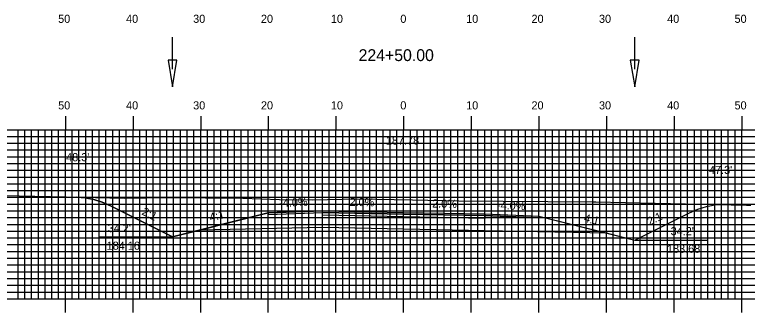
# Model space of a CAD drawing. Extents: x 1797994 to 1798337, y 442591 to 442811.
# Drawn here: x 1798102.5 to 1798210.8, y 442696.7 to 442740.7 of the extents above; entities that cross this region are included whole.
import ezdxf

# ---------------------------------------------------------------- set-up
doc = ezdxf.new("R2010")
doc.units = 0
for name, color, linetype in [('ANNOTATION', 7, 'Continuous'), ('D_Drainage_Ditch_Line', 7, 'Continuous'), ('D_Roadway_Centerline', 7, 'Continuous'), ('D_Roadway_Centerline_Text', 7, 'Continuous'), ('D_Roadway_Edge_Shoulder', 7, 'Continuous'), ('D_Roadway_Edge_TW', 7, 'Continuous'), ('D_Roadway_Pavement', 7, 'Continuous'), ('D_Roadway_SlopeLines', 7, 'Continuous'), ('D_Roadway_SubGrade', 7, 'Continuous'), ('D_Text_Standard', 7, 'Continuous'), ('H_V ANNOTATION', 7, 'Continuous'), ('MAJOR', 7, 'Continuous'), ('MINOR', 7, 'Continuous'), ('PDRAIN', 7, 'Continuous'), ('S_Roadway_Centerline', 7, 'Continuous')]:
    doc.layers.add(name, color=color, linetype=linetype)

msp = doc.modelspace()

# ---------------------------------------------------------------- linework, layer by layer
at = {"layer": 'D_Drainage_Ditch_Line'}
for p, q in [((1798125.78, 442732.63), (1798125.78, 442737.33)), ((1798194.13, 442732.63), (1798194.13, 442737.33))]:
    msp.add_line(p, q, dxfattribs=at)
for points in [[(1798126.44, 442733.94), (1798125.13, 442733.94), (1798125.78, 442730)], [(1798194.79, 442733.94), (1798193.48, 442733.94), (1798194.13, 442730)]]:
    msp.add_lwpolyline(points, close=True, dxfattribs=at)
at = {"layer": 'D_Roadway_Centerline'}
msp.add_lwpolyline([(1798111.64, 442713.71), (1798112.89, 442713.6), (1798114.14, 442713.35), (1798115.39, 442712.95), (1798116.64, 442712.4), (1798125.78, 442707.83), (1798129.78, 442708.83), (1798139.96, 442711.37), (1798147.96, 442711.69), (1798159.96, 442711.45), (1798171.96, 442711.21), (1798179.96, 442710.89), (1798190.13, 442708.35), (1798194.13, 442707.35), (1798202.23, 442711.4), (1798203.48, 442711.94), (1798204.73, 442712.32), (1798205.98, 442712.54), (1798207.23, 442712.59)], dxfattribs=at)
at = {"layer": 'D_Roadway_Edge_Shoulder'}
for points in [[(1798147.96, 442711.69), (1798139.96, 442711.37), (1798139.96, 442711.12), (1798147.96, 442711.44)], [(1798171.96, 442711.21), (1798179.96, 442710.89), (1798179.96, 442710.64), (1798171.96, 442710.96)]]:
    msp.add_lwpolyline(points, close=True, dxfattribs=at)
at = {"layer": 'D_Roadway_Edge_TW'}
msp.add_lwpolyline([(1798147.96, 442711.44), (1798147.96, 442711.69), (1798159.96, 442711.45), (1798171.96, 442711.21), (1798171.96, 442710.96), (1798159.96, 442711.2)], close=True, dxfattribs=at)
at = {"layer": 'D_Roadway_Pavement'}
msp.add_lwpolyline([(1798147.96, 442711.02), (1798147.96, 442711.44), (1798159.96, 442711.2), (1798171.96, 442710.96), (1798171.96, 442710.54), (1798159.96, 442710.78)], close=True, dxfattribs=at)
at = {"layer": 'D_Roadway_SlopeLines'}
for points in [[(1798125.78, 442707.83), (1798116.64, 442712.4), (1798115.39, 442712.95), (1798114.14, 442713.35), (1798112.89, 442713.6), (1798111.64, 442713.71)], [(1798194.13, 442707.35), (1798202.23, 442711.4), (1798203.48, 442711.94), (1798204.73, 442712.32), (1798205.98, 442712.54), (1798207.23, 442712.59)], [(1798139.96, 442711.37), (1798125.78, 442707.83)], [(1798179.96, 442710.89), (1798194.13, 442707.35)]]:
    msp.add_lwpolyline(points, dxfattribs=at)
at = {"layer": 'D_Roadway_SubGrade'}
msp.add_lwpolyline([(1798147.96, 442709.19), (1798129.78, 442708.83), (1798139.96, 442711.37), (1798139.96, 442711.12), (1798147.96, 442711.44), (1798159.96, 442711.2), (1798171.96, 442710.96), (1798179.96, 442710.64), (1798179.96, 442710.89), (1798190.13, 442708.35), (1798171.96, 442708.71), (1798159.96, 442708.95)], close=True, dxfattribs=at)
at = {"layer": 'MAJOR'}
for p, q in [((1798109.96, 442725.67), (1798109.96, 442723.67)), ((1798119.96, 442725.67), (1798119.96, 442723.67)), ((1798129.96, 442725.67), (1798129.96, 442723.67)), ((1798139.96, 442725.67), (1798139.96, 442723.67)), ((1798149.96, 442725.67), (1798149.96, 442723.67)), ((1798159.96, 442725.67), (1798159.96, 442723.67)), ((1798169.96, 442725.67), (1798169.96, 442723.67)), ((1798179.96, 442725.67), (1798179.96, 442723.67)), ((1798189.96, 442725.67), (1798189.96, 442723.67)), ((1798199.96, 442725.67), (1798199.96, 442723.67)), ((1798209.96, 442725.67), (1798209.96, 442723.67)), ((1798019.96, 442723.67), (1798299.96, 442723.67)), ((1798019.96, 442723.67), (1798299.96, 442723.67)), ((1798109.96, 442698.67), (1798109.96, 442723.67)), ((1798119.96, 442698.67), (1798119.96, 442723.67)), ((1798129.96, 442698.67), (1798129.96, 442723.67)), ((1798139.96, 442698.67), (1798139.96, 442723.67)), ((1798149.96, 442698.67), (1798149.96, 442723.67)), ((1798159.96, 442698.67), (1798159.96, 442723.67)), ((1798169.96, 442698.67), (1798169.96, 442723.67)), ((1798179.96, 442698.67), (1798179.96, 442723.67)), ((1798189.96, 442698.67), (1798189.96, 442723.67)), ((1798199.96, 442698.67), (1798199.96, 442723.67)), ((1798209.96, 442698.67), (1798209.96, 442723.67)), ((1798019.96, 442718.67), (1798299.96, 442718.67)), ((1798019.96, 442713.67), (1798299.96, 442713.67)), ((1798019.96, 442708.67), (1798299.96, 442708.67)), ((1798019.96, 442703.67), (1798299.96, 442703.67)), ((1798019.96, 442698.67), (1798299.96, 442698.67)), ((1798019.96, 442698.67), (1798299.96, 442698.67)), ((1798109.96, 442696.66), (1798109.96, 442698.67)), ((1798119.96, 442696.66), (1798119.96, 442698.67)), ((1798129.96, 442696.66), (1798129.96, 442698.67)), ((1798139.96, 442696.66), (1798139.96, 442698.67)), ((1798149.96, 442696.66), (1798149.96, 442698.67)), ((1798159.96, 442696.66), (1798159.96, 442698.67)), ((1798169.96, 442696.66), (1798169.96, 442698.67)), ((1798179.96, 442696.66), (1798179.96, 442698.67)), ((1798189.96, 442696.66), (1798189.96, 442698.67)), ((1798199.96, 442696.66), (1798199.96, 442698.67)), ((1798209.96, 442696.66), (1798209.96, 442698.67))]:
    msp.add_line(p, q, dxfattribs=at)
at = {"layer": 'MINOR'}
for p, q in [((1798102.96, 442698.67), (1798102.96, 442723.67)), ((1798103.96, 442698.67), (1798103.96, 442723.67)), ((1798104.96, 442698.67), (1798104.96, 442723.67)), ((1798105.96, 442698.67), (1798105.96, 442723.67)), ((1798106.96, 442698.67), (1798106.96, 442723.67)), ((1798107.96, 442698.67), (1798107.96, 442723.67)), ((1798108.96, 442698.67), (1798108.96, 442723.67)), ((1798110.96, 442698.67), (1798110.96, 442723.67)), ((1798111.96, 442698.67), (1798111.96, 442723.67)), ((1798112.96, 442698.67), (1798112.96, 442723.67)), ((1798113.96, 442698.67), (1798113.96, 442723.67)), ((1798114.96, 442698.67), (1798114.96, 442723.67)), ((1798115.96, 442698.67), (1798115.96, 442723.67)), ((1798116.96, 442698.67), (1798116.96, 442723.67)), ((1798117.96, 442698.67), (1798117.96, 442723.67)), ((1798118.96, 442698.67), (1798118.96, 442723.67)), ((1798120.96, 442698.67), (1798120.96, 442723.67)), ((1798121.96, 442698.67), (1798121.96, 442723.67)), ((1798122.96, 442698.67), (1798122.96, 442723.67)), ((1798123.96, 442698.67), (1798123.96, 442723.67)), ((1798124.96, 442698.67), (1798124.96, 442723.67)), ((1798125.96, 442698.67), (1798125.96, 442723.67)), ((1798126.96, 442698.67), (1798126.96, 442723.67)), ((1798127.96, 442698.67), (1798127.96, 442723.67)), ((1798128.96, 442698.67), (1798128.96, 442723.67)), ((1798130.96, 442698.67), (1798130.96, 442723.67)), ((1798131.96, 442698.67), (1798131.96, 442723.67)), ((1798132.96, 442698.67), (1798132.96, 442723.67)), ((1798133.96, 442698.67), (1798133.96, 442723.67)), ((1798134.96, 442698.67), (1798134.96, 442723.67)), ((1798135.96, 442698.67), (1798135.96, 442723.67)), ((1798136.96, 442698.67), (1798136.96, 442723.67)), ((1798137.96, 442698.67), (1798137.96, 442723.67)), ((1798138.96, 442698.67), (1798138.96, 442723.67)), ((1798140.96, 442698.67), (1798140.96, 442723.67)), ((1798141.96, 442698.67), (1798141.96, 442723.67)), ((1798142.96, 442698.67), (1798142.96, 442723.67)), ((1798143.96, 442698.67), (1798143.96, 442723.67)), ((1798144.96, 442698.67), (1798144.96, 442723.67)), ((1798145.96, 442698.67), (1798145.96, 442723.67)), ((1798146.96, 442698.67), (1798146.96, 442723.67)), ((1798147.96, 442698.67), (1798147.96, 442723.67)), ((1798148.96, 442698.67), (1798148.96, 442723.67)), ((1798150.96, 442698.67), (1798150.96, 442723.67)), ((1798151.96, 442698.67), (1798151.96, 442723.67)), ((1798152.96, 442698.67), (1798152.96, 442723.67)), ((1798153.96, 442698.67), (1798153.96, 442723.67)), ((1798154.96, 442698.67), (1798154.96, 442723.67)), ((1798155.96, 442698.67), (1798155.96, 442723.67)), ((1798156.96, 442698.67), (1798156.96, 442723.67)), ((1798157.96, 442698.67), (1798157.96, 442723.67)), ((1798158.96, 442698.67), (1798158.96, 442723.67)), ((1798160.96, 442698.67), (1798160.96, 442723.67)), ((1798161.96, 442698.67), (1798161.96, 442723.67)), ((1798162.96, 442698.67), (1798162.96, 442723.67)), ((1798163.96, 442698.67), (1798163.96, 442723.67)), ((1798164.96, 442698.67), (1798164.96, 442723.67)), ((1798165.96, 442698.67), (1798165.96, 442723.67)), ((1798166.96, 442698.67), (1798166.96, 442723.67)), ((1798167.96, 442698.67), (1798167.96, 442723.67)), ((1798168.96, 442698.67), (1798168.96, 442723.67)), ((1798170.96, 442698.67), (1798170.96, 442723.67)), ((1798171.96, 442698.67), (1798171.96, 442723.67)), ((1798172.96, 442698.67), (1798172.96, 442723.67)), ((1798173.96, 442698.67), (1798173.96, 442723.67)), ((1798174.96, 442698.67), (1798174.96, 442723.67)), ((1798175.96, 442698.67), (1798175.96, 442723.67)), ((1798176.96, 442698.67), (1798176.96, 442723.67)), ((1798177.96, 442698.67), (1798177.96, 442723.67)), ((1798178.96, 442698.67), (1798178.96, 442723.67)), ((1798180.96, 442698.67), (1798180.96, 442723.67)), ((1798181.96, 442698.67), (1798181.96, 442723.67)), ((1798182.96, 442698.67), (1798182.96, 442723.67)), ((1798183.96, 442698.67), (1798183.96, 442723.67)), ((1798184.96, 442698.67), (1798184.96, 442723.67)), ((1798185.96, 442698.67), (1798185.96, 442723.67)), ((1798186.96, 442698.67), (1798186.96, 442723.67)), ((1798187.96, 442698.67), (1798187.96, 442723.67)), ((1798188.96, 442698.67), (1798188.96, 442723.67)), ((1798190.96, 442698.67), (1798190.96, 442723.67)), ((1798191.96, 442698.67), (1798191.96, 442723.67)), ((1798192.96, 442698.67), (1798192.96, 442723.67)), ((1798193.96, 442698.67), (1798193.96, 442723.67)), ((1798194.96, 442698.67), (1798194.96, 442723.67)), ((1798195.96, 442698.67), (1798195.96, 442723.67)), ((1798196.96, 442698.67), (1798196.96, 442723.67)), ((1798197.96, 442698.67), (1798197.96, 442723.67)), ((1798198.96, 442698.67), (1798198.96, 442723.67)), ((1798200.96, 442698.67), (1798200.96, 442723.67)), ((1798201.96, 442698.67), (1798201.96, 442723.67)), ((1798202.96, 442698.67), (1798202.96, 442723.67)), ((1798203.96, 442698.67), (1798203.96, 442723.67)), ((1798204.96, 442698.67), (1798204.96, 442723.67)), ((1798205.96, 442698.67), (1798205.96, 442723.67)), ((1798206.96, 442698.67), (1798206.96, 442723.67)), ((1798207.96, 442698.67), (1798207.96, 442723.67)), ((1798208.96, 442698.67), (1798208.96, 442723.67)), ((1798019.96, 442722.67), (1798299.96, 442722.67)), ((1798019.96, 442721.67), (1798299.96, 442721.67)), ((1798019.96, 442720.67), (1798299.96, 442720.67)), ((1798019.96, 442719.67), (1798299.96, 442719.67)), ((1798019.96, 442717.67), (1798299.96, 442717.67)), ((1798019.96, 442716.67), (1798299.96, 442716.67)), ((1798019.96, 442715.67), (1798299.96, 442715.67)), ((1798019.96, 442714.67), (1798299.96, 442714.67)), ((1798019.96, 442712.67), (1798299.96, 442712.67)), ((1798019.96, 442711.67), (1798299.96, 442711.67)), ((1798019.96, 442710.67), (1798299.96, 442710.67)), ((1798019.96, 442709.67), (1798299.96, 442709.67)), ((1798019.96, 442707.67), (1798299.96, 442707.67)), ((1798019.96, 442706.67), (1798299.96, 442706.67)), ((1798019.96, 442705.67), (1798299.96, 442705.67)), ((1798019.96, 442704.67), (1798299.96, 442704.67)), ((1798019.96, 442702.67), (1798299.96, 442702.67)), ((1798019.96, 442701.67), (1798299.96, 442701.67)), ((1798019.96, 442700.67), (1798299.96, 442700.67)), ((1798019.96, 442699.67), (1798299.96, 442699.67))]:
    msp.add_line(p, q, dxfattribs=at)
at = {"layer": 'PDRAIN'}
for p, q in [((1798115.06, 442707.83), (1798125.78, 442707.83)), ((1798194.13, 442707.35), (1798204.9, 442707.35))]:
    msp.add_line(p, q, dxfattribs=at)
at = {"layer": 'S_Roadway_Centerline'}
msp.add_lwpolyline([(1798095.45, 442713.94), (1798103.11, 442713.87), (1798110.05, 442713.75), (1798118.68, 442713.53), (1798125.09, 442713.63), (1798136.17, 442713.53), (1798141.61, 442713.35), (1798146.48, 442713.31), (1798153.15, 442713.43), (1798161.3, 442713.29), (1798168.15, 442713.17), (1798187.86, 442712.98), (1798188.4, 442712.98), (1798197.15, 442712.81), (1798210.64, 442712.52), (1798211.32, 442712.52)], dxfattribs=at)

# ---------------------------------------------------------------- texts
at = {"layer": 'ANNOTATION'}
for s, rotation, p in [('-4.0%', 2.2906, (1798141.59, 442712.24)), ('2.0%', 358.8542, (1798151.96, 442712.41)), ('-2.0%', 358.8542, (1798163.64, 442712.18)), ('-4.0%', 357.7094, (1798173.75, 442711.94)), ('2:1', 333.4349, (1798121.15, 442711.18)), ('4:1', 14.0362, (1798131.41, 442710.09)), ('2:1', 26.5651, (1798196.33, 442709.48)), ('4:1', 345.9638, (1798186.55, 442710.1))]:
    msp.add_text(s, height=1.2, rotation=rotation, dxfattribs=at).set_placement(p)
for s, p in [("34.2'", (1798116.22, 442708.52)), ("34.2'", (1798199.44, 442708.07)), ('184.16', (1798116.06, 442705.92)), ('183.68', (1798198.91, 442705.47))]:
    msp.add_text(s, height=1.2, dxfattribs=at).set_placement(p)
at = {"layer": 'D_Roadway_Centerline'}
for s, p in [('C', (1798159.95, 442711.45)), ('L', (1798159.96, 442711.44))]:
    msp.add_text(s, height=0.0146, dxfattribs=at).set_placement(p)
at = {"layer": 'D_Roadway_Centerline_Text'}
msp.add_text('187.78', height=1.2, dxfattribs=at).set_placement((1798157.35, 442721.48))
at = {"layer": 'D_Text_Standard'}
for s, p in [("48.3'", (1798110.07, 442719.01)), ("47.3'", (1798205.12, 442717.12))]:
    msp.add_text(s, height=1.2, dxfattribs=at).set_placement(p)
at = {"layer": 'H_V ANNOTATION'}
for s, height, p in [('50', 1.2, (1798108.89, 442739.47)), ('40', 1.2, (1798118.93, 442739.47)), ('30', 1.2, (1798128.85, 442739.47)), ('20', 1.2, (1798138.87, 442739.47)), ('10', 1.2, (1798149.21, 442739.47)), ('0', 1.2, (1798159.48, 442739.47)), ('10', 1.2, (1798169.21, 442739.47)), ('20', 1.2, (1798178.87, 442739.47)), ('30', 1.2, (1798188.85, 442739.47)), ('40', 1.2, (1798198.93, 442739.47)), ('50', 1.2, (1798208.89, 442739.47)), ('224+50.00', 1.75, (1798153.31, 442733.82)), ('50', 1.2, (1798108.89, 442726.67)), ('40', 1.2, (1798118.93, 442726.67)), ('30', 1.2, (1798128.85, 442726.67)), ('20', 1.2, (1798138.87, 442726.67)), ('10', 1.2, (1798149.21, 442726.67)), ('0', 1.2, (1798159.48, 442726.67)), ('10', 1.2, (1798169.21, 442726.67)), ('20', 1.2, (1798178.87, 442726.67)), ('30', 1.2, (1798188.85, 442726.67)), ('40', 1.2, (1798198.93, 442726.67)), ('50', 1.2, (1798208.89, 442726.67))]:
    msp.add_text(s, height=height, dxfattribs=at).set_placement(p)

doc.saveas('drawing.dxf')
